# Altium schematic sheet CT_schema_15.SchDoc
size 390 x 385 mm
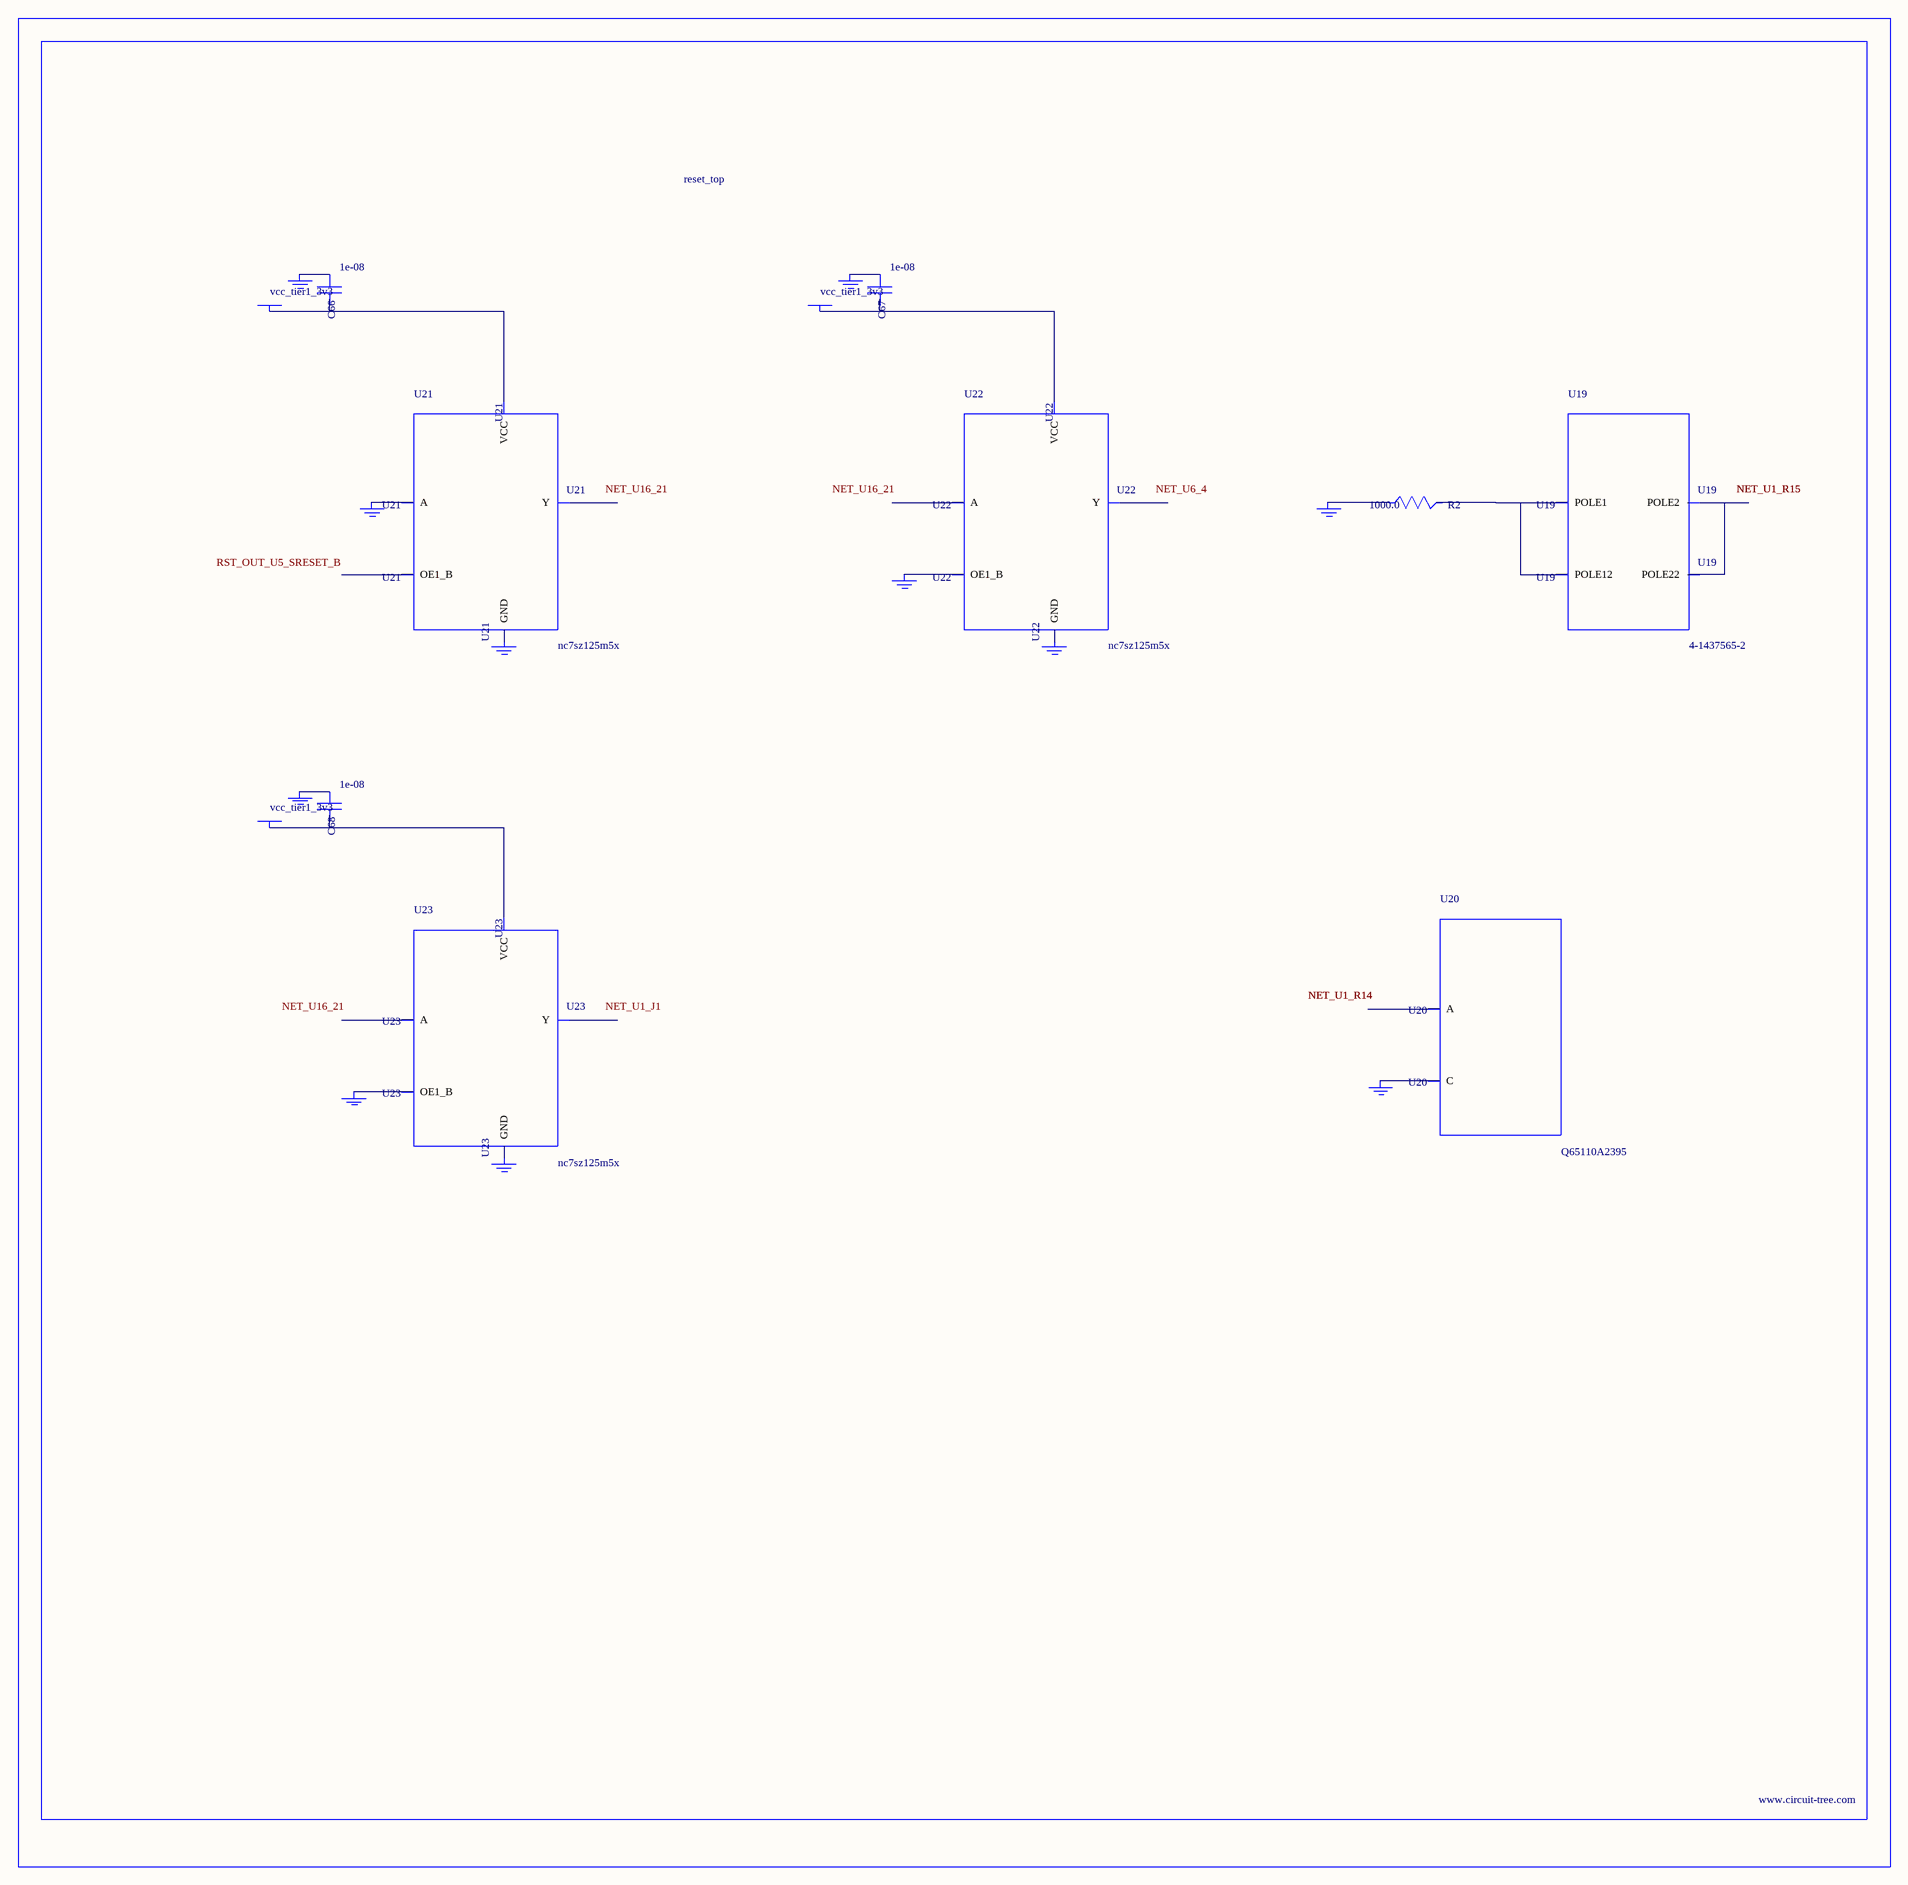
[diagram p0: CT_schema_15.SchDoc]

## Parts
BORDER14  (no value)
C66  1e-08  [C0402]
C67  1e-08  [C0402]
C68  1e-08  [C0402]
GND_INSTANCE_14_0  (no value)
GND_INSTANCE_14_1  (no value)
GND_INSTANCE_14_2  (no value)
GND_INSTANCE_14_3  (no value)
GND_INSTANCE_14_4  (no value)
GND_INSTANCE_14_5  (no value)
GND_INSTANCE_14_6  (no value)
GND_INSTANCE_14_7  (no value)
GND_INSTANCE_14_8  (no value)
GND_INSTANCE_14_9  (no value)
GND_INSTANCE_14_10  (no value)
POWER_INSTANCE_14_0  vcc_tier1_3v3
POWER_INSTANCE_14_1  vcc_tier1_3v3
POWER_INSTANCE_14_2  vcc_tier1_3v3
R2  1000.0  [R0603]
U19  4-1437565-2  [SW_4-1437565-2]
U20  Q65110A2395  [LGM67K-G1J2-24-Z]
U21  nc7sz125m5x  [NC7SZ125M5X]
U22  nc7sz125m5x  [NC7SZ125M5X]
U23  nc7sz125m5x  [NC7SZ125M5X]

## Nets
NetC66_1: C66.1 GND_INSTANCE_14_2.0(GND)
NetC66_2: C66.2 POWER_INSTANCE_14_0.0(PWR) U21.5(VCC)
NetC67_1: C67.1 GND_INSTANCE_14_5.0(GND)
NetC67_2: C67.2 POWER_INSTANCE_14_1.0(PWR) U22.5(VCC)
NetC68_1: C68.1 GND_INSTANCE_14_8.0(GND)
NetC68_2: C68.2 POWER_INSTANCE_14_2.0(PWR) U23.5(VCC)
NetGND_INSTANCE_14_0_0: GND_INSTANCE_14_0.0(GND) R2.1
NetGND_INSTANCE_14_1_0: GND_INSTANCE_14_1.0(GND) U20.C
NetGND_INSTANCE_14_3_0: GND_INSTANCE_14_3.0(GND) U21.2(A)
NetGND_INSTANCE_14_4_0: GND_INSTANCE_14_4.0(GND) U21.3(GND)
NetGND_INSTANCE_14_6_0: GND_INSTANCE_14_6.0(GND) U22.1(OE1_B)
NetGND_INSTANCE_14_7_0: GND_INSTANCE_14_7.0(GND) U22.3(GND)
NetGND_INSTANCE_14_9_0: GND_INSTANCE_14_9.0(GND) U23.1(OE1_B)
NetGND_INSTANCE_14_10_0: GND_INSTANCE_14_10.0(GND) U23.3(GND)
NetR2_2: R2.2 U19.1(POLE1) U19.2(POLE12)
NetU19_3: U19.3(POLE2) U19.4(POLE22)

Not connected (* = marked no-connect by the designer): U20 A; U21 1(OE1_B) 4(Y); U22 2(A) 4(Y); U23 2(A) 4(Y)

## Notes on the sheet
- Labels drawn without touching a wire or pin: NET_U1_J1, NET_U6_4, NET_U16_21, RST_OUT_U5_SRESET_B

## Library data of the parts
BORDER14 = BORDER_PAGE14
C66-C68 = C0402C103K3RAC
GND_INSTANCE_14_0-GND_INSTANCE_14_10 = GND
POWER_INSTANCE_14_0-POWER_INSTANCE_14_2 = PWR
R2 = RC0603JR-071KL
